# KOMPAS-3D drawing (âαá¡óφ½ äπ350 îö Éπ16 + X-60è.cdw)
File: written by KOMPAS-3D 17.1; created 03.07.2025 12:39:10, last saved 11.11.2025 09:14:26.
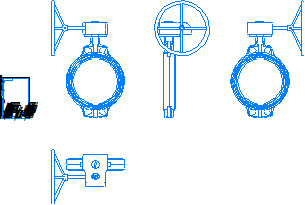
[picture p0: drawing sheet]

Sheet 1: A4, portrait

Title block, sheet 1: sheets: 1; sheet format: A4; stored path: \\adlc.lan\data\АДЛ_ПКД\3D-модели\ADL production\Дисковые поворотные затворы ГРАНВЭЛ\межфланцевый с китайским редуктором Ру16\KOMPAS 2D\Гранвэл Ду350 МФ Ру16 + X-60К.cdw

Views: Вид 1, Снизу, Проекционный вид 2, Проекционный вид 3, Проекционный вид 4
Referenced files in \\adlc.lan\data\АДЛ_ПКД\3D-модели\ADL production\Дисковые поворотные затворы ГРАНВЭЛ\межфланцевый с китайским редуктором Ру16\KOMPAS 3D\: Гранвэл Ду350 МФ Ру16 + X-60К.m3d
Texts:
  Andrey
  АДЛ
Dimensions and other numbers on the sheet: 1:1; 1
